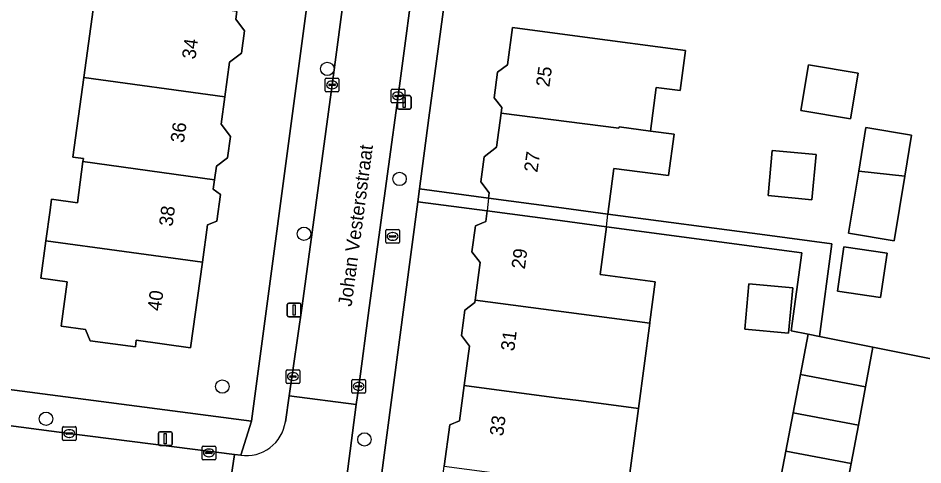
# Model space of a CAD drawing. Extents: x 161258 to 161838, y 380833 to 381727.
# Drawn here: x 161720.1 to 161786.2, y 381576.8 to 381609.4 of the extents above; entities that cross this region are included whole.
import ezdxf

# ---------------------------------------------------------------- set-up
doc = ezdxf.new("R2010")
doc.units = 0
for name, color, linetype in [('IMGEO_Boom', 7, 'Continuous'), ('IMGEO_Brandkraan', 7, 'Continuous'), ('IMGEO_Erf', 7, 'Continuous'), ('IMGEO_Kolk', 7, 'Continuous'), ('IMGEO_Lichtmast', 7, 'Continuous'), ('IMGEO_Openbare_ruimte_label', 7, 'Continuous'), ('IMGEO_Pand', 7, 'Continuous'), ('IMGEO_Pand_nummerreeks', 7, 'Continuous'), ('IMGEO_Pand_overbouw', 7, 'Continuous'), ('IMGEO_Rijbaan_lokaal_open', 7, 'Continuous'), ('IMGEO_Voetpad_open', 7, 'Continuous')]:
    doc.layers.add(name, color=color, linetype=linetype)

msp = doc.modelspace()

# ---------------------------------------------------------------- linework, layer by layer
at = {"layer": 'IMGEO_Boom'}
for centre in [(161742.644, 381605.719), (161747.918, 381597.678), (161740.94, 381593.674), (161734.975, 381582.509), (161722.096, 381580.156), (161745.355, 381578.647)]:
    msp.add_circle(centre, 0.489, dxfattribs=at)
at = {"layer": 'IMGEO_Brandkraan'}
for p, q in [((161746.909, 381593.052), (161746.909, 381593.904)), ((161746.984, 381593.978), (161747.836, 381593.978)), ((161747.168, 381593.472), (161747.168, 381593.484)), ((161747.211, 381593.521), (161747.609, 381593.521)), ((161747.397, 381593.758), (161747.422, 381593.758)), ((161747.652, 381593.484), (161747.652, 381593.472)), ((161747.91, 381593.904), (161747.91, 381593.052)), ((161747.836, 381592.978), (161746.984, 381592.978)), ((161747.606, 381593.435), (161747.208, 381593.435)), ((161747.42, 381593.198), (161747.395, 381593.198))]:
    msp.add_line(p, q, dxfattribs=at)
for points in [[(161746.909, 381593.052), (161746.909, 381593.904)], [(161746.984, 381593.978), (161747.836, 381593.978)], [(161747.91, 381593.904), (161747.91, 381593.052)], [(161747.836, 381592.978), (161746.984, 381592.978)]]:
    msp.add_lwpolyline(points, dxfattribs=at)
for centre, radius, start, end in [((161746.986, 381593.902), 0.0765, 91.55205, 178.44795), ((161746.986, 381593.902), 0.0765, 91.55205, 178.44795), ((161747.208, 381593.481), 0.0403, 85.87752, 175.75265), ((161747.205, 381593.471), 0.0366, 178.93798, 274.71019), ((161747.609, 381593.478), 0.043, 264.86636, 352.45326), ((161747.613, 381593.483), 0.0386, 1.73085, 96.63898), ((161747.834, 381593.902), 0.0765, 1.55205, 88.44795), ((161747.834, 381593.902), 0.0765, 1.55205, 88.44795), ((161746.986, 381593.054), 0.0765, 181.55205, 268.44795), ((161746.986, 381593.054), 0.0765, 181.55205, 268.44795), ((161747.834, 381593.054), 0.0765, 271.55205, 358.44795), ((161747.834, 381593.054), 0.0765, 271.55205, 358.44795)]:
    msp.add_arc(centre, radius, start, end, dxfattribs=at)
for centre, major_axis, ratio, start_param, end_param in [((161747.396, 381593.478), (-0.387, 0.002), 0.722429, 4.712389, 7.853982), ((161747.421, 381593.478), (-0.39, 0.002), 0.717154, 1.570796, 4.712389)]:
    msp.add_ellipse(centre, major_axis=major_axis, ratio=ratio, start_param=start_param, end_param=end_param, dxfattribs=at)
at = {"layer": 'IMGEO_Erf'}
for points in [[(161713.989, 381583.006), (161737.106, 381579.978), (161744.895, 381638.467)], [(161754.739, 381636.721), (161750.063, 381602.151), (161749.372, 381596.944), (161754.417, 381596.275), (161754.467, 381596.651), (161753.849, 381597.46), (161754.094, 381599.302), (161755.001, 381599.996), (161755.332, 381602.48), (161755.386, 381602.887), (161754.835, 381603.608), (161755.082, 381605.472), (161755.8, 381606.021), (161756.162, 381608.746), (161761.094, 381608.09), (161768.811, 381607.063), (161768.42, 381604.129), (161766.677, 381604.361), (161766.253, 381601.17), (161767.974, 381600.941), (161767.572, 381597.922), (161763.586, 381598.452), (161763.142, 381595.114), (161774.615, 381593.589), (161779.503, 381592.939), (161778.603, 381586.17), (161782.505, 381585.389), (161793.109, 381583.267)], [(161736.036, 381609.917), (161735.957, 381609.341), (161736.595, 381608.501), (161736.372, 381606.876), (161735.502, 381606.216), (161735.153, 381603.676), (161734.88, 381601.684), (161735.565, 381600.781), (161735.351, 381599.222), (161734.546, 381598.611), (161734.41, 381597.62), (161734.315, 381596.933), (161734.833, 381596.531), (161734.568, 381594.595), (161733.893, 381594.319), (161733.518, 381591.586), (161732.661, 381585.347), (161728.687, 381585.893), (161728.621, 381585.409), (161725.321, 381585.862), (161724.988, 381586.68), (161723.2, 381586.926), (161723.645, 381590.171), (161721.713, 381590.436), (161722.086, 381593.156), (161722.393, 381595.39), (161722.504, 381596.198), (161724.384, 381595.939), (161724.796, 381598.941), (161724.827, 381599.167), (161724.053, 381599.273), (161724.852, 381605.092), (161725.709, 381611.334)], [(161775.614, 381574.978), (161776.143, 381577.779), (161776.673, 381580.581), (161777.203, 381583.382), (161777.762, 381586.338), (161776.539, 381586.583), (161777.298, 381592.286), (161763.039, 381594.183), (161762.576, 381590.704), (161766.605, 381590.169), (161766.211, 381587.209), (161766.203, 381587.145), (161765.382, 381580.905), (161764.569, 381574.925)]]:
    msp.add_lwpolyline(points, dxfattribs=at)
for points in [[(161780.861, 381602.07), (161777.229, 381602.671), (161777.782, 381606.014), (161781.414, 381605.413)], [(161781.469, 381598.253), (161781.994, 381601.428), (161785.32, 381600.877), (161784.824, 381597.882), (161784.043, 381593.161), (161780.717, 381593.711)], [(161778.047, 381596.16), (161774.843, 381596.459), (161775.152, 381599.763), (161778.356, 381599.464)], [(161753.021, 381585.471), (161752.436, 381586.236), (161752.683, 381588.09), (161753.412, 381588.649), (161753.435, 381588.827), (161753.8, 381591.566), (161753.207, 381592.341), (161753.462, 381594.259), (161754.222, 381594.573), (161754.324, 381595.343), (161749.249, 381596.016), (161746.014, 381571.629), (161751.151, 381570.945), (161751.47, 381573.34), (161750.85, 381574.15), (161751.188, 381576.688), (161751.591, 381579.718), (161752.295, 381580.008), (161752.637, 381582.578)], [(161783.056, 381589.01), (161779.906, 381589.473), (161780.383, 381592.716), (161783.533, 381592.254)], [(161773.445, 381590.017), (161776.649, 381589.718), (161776.341, 381586.414), (161773.137, 381586.713)]]:
    msp.add_lwpolyline(points, close=True, dxfattribs=at)
at = {"layer": 'IMGEO_Kolk'}
for p, q in [((161742.493, 381604.122), (161742.493, 381604.974)), ((161742.568, 381605.048), (161743.42, 381605.048)), ((161742.981, 381604.828), (161743.006, 381604.828)), ((161743.494, 381604.974), (161743.494, 381604.122)), ((161743.42, 381604.048), (161742.568, 381604.048)), ((161742.752, 381604.542), (161742.752, 381604.554)), ((161743.19, 381604.505), (161742.792, 381604.505)), ((161742.795, 381604.591), (161743.193, 381604.591)), ((161743.004, 381604.268), (161742.979, 381604.268)), ((161743.236, 381604.554), (161743.236, 381604.542)), ((161747.311, 381603.316), (161747.311, 381604.168)), ((161747.386, 381604.242), (161748.238, 381604.242)), ((161747.799, 381604.022), (161747.824, 381604.022)), ((161748.312, 381604.168), (161748.312, 381603.316)), ((161747.57, 381603.736), (161747.57, 381603.748)), ((161748.008, 381603.699), (161747.61, 381603.699)), ((161747.613, 381603.785), (161748.011, 381603.785)), ((161747.822, 381603.462), (161747.797, 381603.462)), ((161748.054, 381603.748), (161748.054, 381603.736)), ((161748.238, 381603.242), (161747.386, 381603.242)), ((161739.633, 381582.813), (161739.633, 381583.665)), ((161739.708, 381583.739), (161740.56, 381583.739)), ((161740.634, 381583.665), (161740.634, 381582.813)), ((161739.892, 381583.233), (161739.892, 381583.245)), ((161740.33, 381583.196), (161739.932, 381583.196)), ((161739.935, 381583.282), (161740.333, 381583.282)), ((161740.144, 381582.959), (161740.119, 381582.959)), ((161740.121, 381583.519), (161740.146, 381583.519)), ((161740.376, 381583.245), (161740.376, 381583.233)), ((161744.434, 381582.099), (161744.434, 381582.951)), ((161744.509, 381583.025), (161745.361, 381583.025)), ((161745.435, 381582.951), (161745.435, 381582.099)), ((161740.56, 381582.739), (161739.708, 381582.739)), ((161744.693, 381582.519), (161744.693, 381582.531)), ((161745.131, 381582.482), (161744.733, 381582.482)), ((161744.736, 381582.568), (161745.134, 381582.568)), ((161744.945, 381582.245), (161744.92, 381582.245)), ((161744.922, 381582.805), (161744.947, 381582.805)), ((161745.177, 381582.531), (161745.177, 381582.519)), ((161745.361, 381582.025), (161744.509, 381582.025)), ((161723.365, 381579.58), (161724.217, 381579.58)), ((161723.29, 381578.654), (161723.29, 381579.506)), ((161723.549, 381579.074), (161723.549, 381579.086)), ((161723.987, 381579.037), (161723.589, 381579.037)), ((161723.592, 381579.123), (161723.99, 381579.123)), ((161723.778, 381579.36), (161723.803, 381579.36)), ((161724.033, 381579.086), (161724.033, 381579.074)), ((161724.291, 381579.506), (161724.291, 381578.654)), ((161724.217, 381578.58), (161723.365, 381578.58)), ((161723.801, 381578.8), (161723.776, 381578.8)), ((161733.491, 381577.236), (161733.491, 381578.088)), ((161733.566, 381578.162), (161734.418, 381578.162)), ((161733.75, 381577.656), (161733.75, 381577.668)), ((161734.188, 381577.619), (161733.79, 381577.619)), ((161733.793, 381577.705), (161734.191, 381577.705)), ((161733.979, 381577.942), (161734.004, 381577.942)), ((161734.234, 381577.668), (161734.234, 381577.656)), ((161734.492, 381578.088), (161734.492, 381577.236)), ((161734.418, 381577.162), (161733.566, 381577.162)), ((161734.002, 381577.382), (161733.977, 381577.382))]:
    msp.add_line(p, q, dxfattribs=at)
for points in [[(161742.493, 381604.122), (161742.493, 381604.974)], [(161742.568, 381605.048), (161743.42, 381605.048)], [(161743.494, 381604.974), (161743.494, 381604.122)], [(161743.42, 381604.048), (161742.568, 381604.048)], [(161747.311, 381603.316), (161747.311, 381604.168)], [(161747.386, 381604.242), (161748.238, 381604.242)], [(161748.312, 381604.168), (161748.312, 381603.316)], [(161748.238, 381603.242), (161747.386, 381603.242)], [(161739.633, 381582.813), (161739.633, 381583.665)], [(161739.708, 381583.739), (161740.56, 381583.739)], [(161740.634, 381583.665), (161740.634, 381582.813)], [(161744.434, 381582.099), (161744.434, 381582.951)], [(161744.509, 381583.025), (161745.361, 381583.025)], [(161745.435, 381582.951), (161745.435, 381582.099)], [(161740.56, 381582.739), (161739.708, 381582.739)], [(161745.361, 381582.025), (161744.509, 381582.025)], [(161723.365, 381579.58), (161724.217, 381579.58)], [(161723.29, 381578.654), (161723.29, 381579.506)], [(161724.291, 381579.506), (161724.291, 381578.654)], [(161724.217, 381578.58), (161723.365, 381578.58)], [(161733.491, 381577.236), (161733.491, 381578.088)], [(161733.566, 381578.162), (161734.418, 381578.162)], [(161734.492, 381578.088), (161734.492, 381577.236)], [(161734.418, 381577.162), (161733.566, 381577.162)]]:
    msp.add_lwpolyline(points, dxfattribs=at)
for centre, radius, start, end in [((161742.57, 381604.972), 0.0765, 91.55205, 178.44795), ((161742.57, 381604.972), 0.0765, 91.55205, 178.44795), ((161743.418, 381604.972), 0.0765, 1.55205, 88.44795), ((161743.418, 381604.972), 0.0765, 1.55205, 88.44795), ((161742.57, 381604.124), 0.0765, 181.55205, 268.44795), ((161742.57, 381604.124), 0.0765, 181.55205, 268.44795), ((161742.792, 381604.551), 0.0403, 85.87752, 175.75265), ((161742.789, 381604.541), 0.0366, 178.93798, 274.71019), ((161743.193, 381604.548), 0.043, 264.86636, 352.45326), ((161743.197, 381604.553), 0.0386, 1.73085, 96.63898), ((161743.418, 381604.124), 0.0765, 271.55205, 358.44795), ((161743.418, 381604.124), 0.0765, 271.55205, 358.44795), ((161747.388, 381604.166), 0.0765, 91.55205, 178.44795), ((161747.388, 381604.166), 0.0765, 91.55205, 178.44795), ((161748.236, 381604.166), 0.0765, 1.55205, 88.44795), ((161748.236, 381604.166), 0.0765, 1.55205, 88.44795), ((161747.61, 381603.745), 0.0403, 85.87752, 175.75265), ((161747.607, 381603.735), 0.0366, 178.93798, 274.71019), ((161748.011, 381603.742), 0.043, 264.86636, 352.45326), ((161748.015, 381603.747), 0.0386, 1.73085, 96.63898), ((161747.388, 381603.318), 0.0765, 181.55205, 268.44795), ((161747.388, 381603.318), 0.0765, 181.55205, 268.44795), ((161748.236, 381603.318), 0.0765, 271.55205, 358.44795), ((161748.236, 381603.318), 0.0765, 271.55205, 358.44795), ((161739.71, 381583.663), 0.0765, 91.55205, 178.44795), ((161739.71, 381583.663), 0.0765, 91.55205, 178.44795), ((161740.558, 381583.663), 0.0765, 1.55205, 88.44795), ((161740.558, 381583.663), 0.0765, 1.55205, 88.44795), ((161739.932, 381583.242), 0.0403, 85.87752, 175.75265), ((161739.929, 381583.232), 0.0366, 178.93798, 274.71019), ((161740.333, 381583.239), 0.043, 264.86636, 352.45326), ((161740.337, 381583.244), 0.0386, 1.73085, 96.63898), ((161744.511, 381582.949), 0.0765, 91.55205, 178.44795), ((161744.511, 381582.949), 0.0765, 91.55205, 178.44795), ((161745.359, 381582.949), 0.0765, 1.55205, 88.44795), ((161745.359, 381582.949), 0.0765, 1.55205, 88.44795), ((161739.71, 381582.815), 0.0765, 181.55205, 268.44795), ((161739.71, 381582.815), 0.0765, 181.55205, 268.44795), ((161740.558, 381582.815), 0.0765, 271.55205, 358.44795), ((161740.558, 381582.815), 0.0765, 271.55205, 358.44795), ((161744.733, 381582.528), 0.0403, 85.87752, 175.75265), ((161744.73, 381582.518), 0.0366, 178.93798, 274.71019), ((161745.134, 381582.525), 0.043, 264.86636, 352.45326), ((161745.138, 381582.53), 0.0386, 1.73085, 96.63898), ((161744.511, 381582.101), 0.0765, 181.55205, 268.44795), ((161744.511, 381582.101), 0.0765, 181.55205, 268.44795), ((161745.359, 381582.101), 0.0765, 271.55205, 358.44795), ((161745.359, 381582.101), 0.0765, 271.55205, 358.44795), ((161723.367, 381579.504), 0.0765, 91.55205, 178.44795), ((161723.367, 381579.504), 0.0765, 91.55205, 178.44795), ((161724.215, 381579.504), 0.0765, 1.55205, 88.44795), ((161724.215, 381579.504), 0.0765, 1.55205, 88.44795), ((161723.589, 381579.083), 0.0403, 85.87752, 175.75265), ((161723.586, 381579.073), 0.0366, 178.93798, 274.71019), ((161723.99, 381579.08), 0.043, 264.86636, 352.45326), ((161723.994, 381579.085), 0.0386, 1.73085, 96.63898), ((161723.367, 381578.656), 0.0765, 181.55205, 268.44795), ((161723.367, 381578.656), 0.0765, 181.55205, 268.44795), ((161724.215, 381578.656), 0.0765, 271.55205, 358.44795), ((161724.215, 381578.656), 0.0765, 271.55205, 358.44795), ((161733.568, 381578.086), 0.0765, 91.55205, 178.44795), ((161733.568, 381578.086), 0.0765, 91.55205, 178.44795), ((161733.79, 381577.665), 0.0403, 85.87752, 175.75265), ((161733.787, 381577.655), 0.0366, 178.93798, 274.71019), ((161734.191, 381577.662), 0.043, 264.86636, 352.45326), ((161734.195, 381577.667), 0.0386, 1.73085, 96.63898), ((161734.416, 381578.086), 0.0765, 1.55205, 88.44795), ((161734.416, 381578.086), 0.0765, 1.55205, 88.44795), ((161733.568, 381577.238), 0.0765, 181.55205, 268.44795), ((161733.568, 381577.238), 0.0765, 181.55205, 268.44795), ((161734.416, 381577.238), 0.0765, 271.55205, 358.44795), ((161734.416, 381577.238), 0.0765, 271.55205, 358.44795)]:
    msp.add_arc(centre, radius, start, end, dxfattribs=at)
for centre, major_axis, ratio, start_param, end_param in [((161742.98, 381604.548), (-0.387, 0.002), 0.722429, 4.712389, 7.853982), ((161743.005, 381604.548), (-0.39, 0.002), 0.717154, 1.570796, 4.712389), ((161747.798, 381603.742), (-0.387, 0.002), 0.722429, 4.712389, 7.853982), ((161747.823, 381603.742), (-0.39, 0.002), 0.717154, 1.570796, 4.712389), ((161740.12, 381583.239), (-0.387, 0.002), 0.722429, 4.712389, 7.853982), ((161740.145, 381583.239), (-0.39, 0.002), 0.717154, 1.570796, 4.712389), ((161744.921, 381582.525), (-0.387, 0.002), 0.722429, 4.712389, 7.853982), ((161744.946, 381582.525), (-0.39, 0.002), 0.717154, 1.570796, 4.712389), ((161723.777, 381579.08), (-0.387, 0.002), 0.722429, 4.712389, 7.853982), ((161723.802, 381579.08), (-0.39, 0.002), 0.717154, 1.570796, 4.712389), ((161733.978, 381577.662), (-0.387, 0.002), 0.722429, 4.712389, 7.853982), ((161734.003, 381577.662), (-0.39, 0.002), 0.717154, 1.570796, 4.712389)]:
    msp.add_ellipse(centre, major_axis=major_axis, ratio=ratio, start_param=start_param, end_param=end_param, dxfattribs=at)
at = {"layer": 'IMGEO_Lichtmast'}
for p, q in [((161747.772, 381602.863), (161747.772, 381603.663)), ((161747.772, 381603.663), (161747.772, 381602.863)), ((161747.872, 381603.763), (161748.662, 381603.763)), ((161748.662, 381603.763), (161747.872, 381603.763)), ((161748.762, 381603.663), (161748.762, 381602.863)), ((161748.762, 381602.863), (161748.762, 381603.663)), ((161748.662, 381602.763), (161747.872, 381602.763)), ((161747.872, 381602.763), (161748.662, 381602.763)), ((161739.723, 381587.709), (161739.723, 381588.509)), ((161739.723, 381588.509), (161739.723, 381587.709)), ((161739.823, 381588.609), (161740.613, 381588.609)), ((161740.613, 381588.609), (161739.823, 381588.609)), ((161740.713, 381588.509), (161740.713, 381587.709)), ((161740.713, 381587.709), (161740.713, 381588.509)), ((161740.613, 381587.609), (161739.823, 381587.609)), ((161739.823, 381587.609), (161740.613, 381587.609)), ((161730.314, 381578.299), (161730.314, 381579.099)), ((161730.314, 381579.099), (161730.314, 381578.299)), ((161730.414, 381579.199), (161731.204, 381579.199)), ((161731.204, 381579.199), (161730.414, 381579.199)), ((161731.304, 381579.099), (161731.304, 381578.299)), ((161731.304, 381578.299), (161731.304, 381579.099)), ((161731.204, 381578.199), (161730.414, 381578.199)), ((161730.414, 381578.199), (161731.204, 381578.199))]:
    msp.add_line(p, q, dxfattribs=at)
for points in [[(161748.192, 381603.638), (161748.342, 381603.638), (161748.342, 381602.888), (161748.192, 381602.888), (161748.192, 381603.638)], [(161740.143, 381588.484), (161740.293, 381588.484), (161740.293, 381587.734), (161740.143, 381587.734), (161740.143, 381588.484)], [(161730.734, 381579.074), (161730.884, 381579.074), (161730.884, 381578.324), (161730.734, 381578.324), (161730.734, 381579.074)]]:
    msp.add_lwpolyline(points, dxfattribs=at)
for centre, start, end in [((161747.872, 381603.663), 90, 180), ((161747.872, 381603.663), 90, 180), ((161748.662, 381603.663), 0, 90), ((161748.662, 381603.663), 360, 90), ((161747.872, 381602.863), 180, 270), ((161747.872, 381602.863), 180, 270), ((161748.662, 381602.863), 270, 0), ((161748.662, 381602.863), 270, 0), ((161739.823, 381588.509), 90, 180), ((161739.823, 381588.509), 90, 180), ((161740.613, 381588.509), 0, 90), ((161740.613, 381588.509), 360, 90), ((161739.823, 381587.709), 180, 270), ((161739.823, 381587.709), 180, 270), ((161740.613, 381587.709), 270, 0), ((161740.613, 381587.709), 270, 0), ((161730.414, 381579.099), 90, 180), ((161730.414, 381579.099), 90, 180), ((161731.204, 381579.099), 0, 90), ((161731.204, 381579.099), 360, 90), ((161730.414, 381578.299), 180, 270), ((161730.414, 381578.299), 180, 270), ((161731.204, 381578.299), 270, 0), ((161731.204, 381578.299), 270, 0)]:
    msp.add_arc(centre, 0.1, start, end, dxfattribs=at)
at = {"layer": 'IMGEO_Pand'}
for points in [[(161724.852, 381605.092), (161735.153, 381603.676), (161735.502, 381606.216), (161736.372, 381606.876), (161736.595, 381608.501), (161735.957, 381609.341), (161736.036, 381609.917), (161731.083, 381610.597), (161725.709, 381611.334)], [(161755.332, 381602.48), (161763.939, 381601.376), (161763.952, 381601.476), (161766.253, 381601.17), (161766.677, 381604.361), (161768.42, 381604.129), (161768.811, 381607.063), (161761.094, 381608.09), (161756.162, 381608.746), (161755.8, 381606.021), (161755.082, 381605.472), (161754.835, 381603.608), (161755.386, 381602.887)], [(161777.229, 381602.671), (161780.861, 381602.07), (161781.414, 381605.413), (161777.782, 381606.014)], [(161724.852, 381605.092), (161724.053, 381599.273), (161724.827, 381599.167), (161724.796, 381598.941), (161734.41, 381597.62), (161734.546, 381598.611), (161735.351, 381599.222), (161735.565, 381600.781), (161734.88, 381601.684), (161735.153, 381603.676)], [(161767.974, 381600.941), (161766.253, 381601.17), (161763.952, 381601.476), (161763.939, 381601.376), (161755.332, 381602.48), (161755.001, 381599.996), (161754.094, 381599.302), (161753.849, 381597.46), (161754.467, 381596.651), (161754.417, 381596.275), (161759.374, 381595.615), (161763.142, 381595.114), (161763.586, 381598.452), (161767.572, 381597.922)], [(161781.469, 381598.253), (161784.824, 381597.882), (161785.32, 381600.877), (161781.994, 381601.428)], [(161778.047, 381596.16), (161778.356, 381599.464), (161775.152, 381599.763), (161774.843, 381596.459)], [(161722.086, 381593.156), (161733.518, 381591.586), (161733.893, 381594.319), (161734.568, 381594.595), (161734.833, 381596.531), (161734.315, 381596.933), (161734.41, 381597.62), (161724.796, 381598.941), (161724.384, 381595.939), (161722.504, 381596.198), (161722.393, 381595.39)], [(161784.824, 381597.882), (161781.469, 381598.253), (161780.717, 381593.711), (161784.043, 381593.161)], [(161753.435, 381588.827), (161766.203, 381587.145), (161766.211, 381587.209), (161766.605, 381590.169), (161762.576, 381590.704), (161763.039, 381594.183), (161759.281, 381594.683), (161754.324, 381595.343), (161754.222, 381594.573), (161753.462, 381594.259), (161753.207, 381592.341), (161753.8, 381591.566)], [(161722.086, 381593.156), (161721.713, 381590.436), (161723.645, 381590.171), (161723.2, 381586.926), (161724.988, 381586.68), (161725.321, 381585.862), (161728.621, 381585.409), (161728.687, 381585.893), (161732.661, 381585.347), (161733.518, 381591.586)], [(161783.533, 381592.254), (161780.383, 381592.716), (161779.906, 381589.473), (161783.056, 381589.01)], [(161776.341, 381586.414), (161776.649, 381589.718), (161773.445, 381590.017), (161773.137, 381586.713)], [(161766.203, 381587.145), (161753.435, 381588.827), (161753.412, 381588.649), (161752.683, 381588.09), (161752.436, 381586.236), (161753.021, 381585.471), (161752.637, 381582.578), (161759.396, 381581.691), (161761.18, 381581.457), (161765.382, 381580.905)], [(161782.505, 381585.389), (161778.603, 381586.17), (161777.762, 381586.338), (161777.203, 381583.382), (161781.962, 381582.492)], [(161781.435, 381579.687), (161781.962, 381582.492), (161777.203, 381583.382), (161776.673, 381580.581)], [(161765.382, 381580.905), (161761.18, 381581.457), (161759.396, 381581.691), (161752.637, 381582.578), (161752.295, 381580.008), (161751.591, 381579.718), (161751.188, 381576.688), (161760.386, 381575.481), (161764.569, 381574.925)], [(161780.909, 381576.885), (161781.435, 381579.687), (161776.673, 381580.581), (161776.143, 381577.779)], [(161780.383, 381574.083), (161780.909, 381576.885), (161776.143, 381577.779), (161775.614, 381574.978)]]:
    msp.add_lwpolyline(points, close=True, dxfattribs=at)
at = {"layer": 'IMGEO_Pand_overbouw'}
msp.add_lwpolyline([(161763.039, 381594.183), (161763.142, 381595.114), (161759.374, 381595.615), (161754.417, 381596.275), (161754.324, 381595.343), (161759.281, 381594.683)], close=True, dxfattribs=at)
at = {"layer": 'IMGEO_Rijbaan_lokaal_open'}
for points in [[(161747.81, 381603.742), (161749.217, 381614.192), (161744.354, 381614.846), (161742.995, 381604.548), (161740.814, 381588.417), (161739.855, 381581.833), (161744.761, 381581.189), (161744.935, 381582.525), (161745.701, 381588.26)], [(161793.109, 381583.267), (161782.505, 381585.389), (161781.962, 381582.492), (161781.435, 381579.687), (161780.909, 381576.885), (161780.383, 381574.083), (161779.83, 381571.134), (161781.308, 381570.848), (161781.392, 381571.272), (161786.642, 381570.271), (161787.039, 381567.813), (161786.221, 381563.671), (161786.11, 381563.693), (161785.277, 381558.94), (161783.734, 381550.581), (161782.826, 381545.664), (161781.913, 381540.72), (161784.977, 381540.142)]]:
    msp.add_lwpolyline(points, close=True, dxfattribs=at)
for points in [[(161744.761, 381581.189), (161739.855, 381581.833), (161739.579, 381579.945)], [(161739.17, 381569.87), (161739.108, 381569.367), (161739.062, 381568.989), (161743.094, 381568.418), (161744.761, 381581.189)], [(161706.214, 381576.473), (161723.234, 381574.173), (161727.337, 381573.606), (161735.113, 381572.49), (161735.86, 381577.557), (161723.791, 381579.08), (161713.619, 381580.431)], [(161736.317, 381577.499), (161735.86, 381577.557), (161735.113, 381572.49), (161736.937, 381572.228)]]:
    msp.add_lwpolyline(points, dxfattribs=at)
msp.add_arc((161736.727, 381580.35), 2.881, 261.81673, 351.91182, dxfattribs=at)
at = {"layer": 'IMGEO_Voetpad_open'}
for points in [[(161744.354, 381614.846), (161744.994, 381619.655), (161746.729, 381632.69), (161746.885, 381633.921), (161747.293, 381636.965), (161747.796, 381641.17), (161745.302, 381641.497), (161744.895, 381638.467), (161737.106, 381579.978), (161736.317, 381577.499)], [(161749.249, 381596.016), (161749.372, 381596.944), (161750.063, 381602.151), (161754.739, 381636.721), (161755.234, 381640.215), (161752.667, 381640.554), (161752.584, 381639.949), (161752.771, 381639.8), (161752.376, 381636.547), (161750.659, 381636.776)], [(161750.568, 381633.878), (161751.755, 381633.691), (161751.695, 381633.24), (161750.369, 381622.752), (161749.866, 381618.991), (161749.217, 381614.192), (161747.81, 381603.742), (161745.701, 381588.26), (161744.935, 381582.525), (161744.761, 381581.189), (161743.094, 381568.418), (161742.572, 381564.421), (161740.738, 381550.621), (161740.508, 381548.595)], [(161739.579, 381579.945), (161739.855, 381581.833), (161740.814, 381588.417), (161742.995, 381604.548), (161744.354, 381614.846)], [(161742.875, 381545.494), (161742.891, 381548.079), (161745.882, 381570.631), (161746.014, 381571.629), (161749.249, 381596.016)]]:
    msp.add_lwpolyline(points, dxfattribs=at)
for points in [[(161763.142, 381595.114), (161759.374, 381595.615), (161754.417, 381596.275), (161749.372, 381596.944), (161749.249, 381596.016), (161754.324, 381595.343), (161759.281, 381594.683), (161763.039, 381594.183), (161777.298, 381592.286), (161776.539, 381586.583), (161777.762, 381586.338), (161778.603, 381586.17), (161779.503, 381592.939), (161774.615, 381593.589)], [(161737.106, 381579.978), (161713.989, 381583.006), (161713.958, 381583.01), (161713.619, 381580.431), (161723.791, 381579.08), (161735.86, 381577.557), (161736.317, 381577.499)]]:
    msp.add_lwpolyline(points, close=True, dxfattribs=at)
msp.add_arc((161736.727, 381580.35), 2.881, 261.81673, 351.91182, dxfattribs=at)

# ---------------------------------------------------------------- texts
at = {"layer": 'IMGEO_Openbare_ruimte_label'}
msp.add_text('Johan Vestersstraat', height=1, rotation=82.41293, dxfattribs=at).set_placement((161744.412, 381588.318))
at = {"layer": 'IMGEO_Pand_nummerreeks'}
for s, rotation, p in [('34', 82.17776, (161733.007, 381606.386)), ('25', 82.0361, (161758.86, 381604.355)), ('36', 82.17776, (161732.168, 381600.275)), ('27', 82.0361, (161757.987, 381598.12)), ('38', 82.17776, (161731.329, 381594.168)), ('29', 82.59018, (161757.074, 381591.051)), ('40', 82.18126, (161730.481, 381587.993)), ('31', 82.59187, (161756.294, 381585.064)), ('33', 82.59187, (161755.487, 381578.852))]:
    msp.add_text(s, height=1, rotation=rotation, dxfattribs=at).set_placement(p)

doc.saveas('drawing.dxf')
